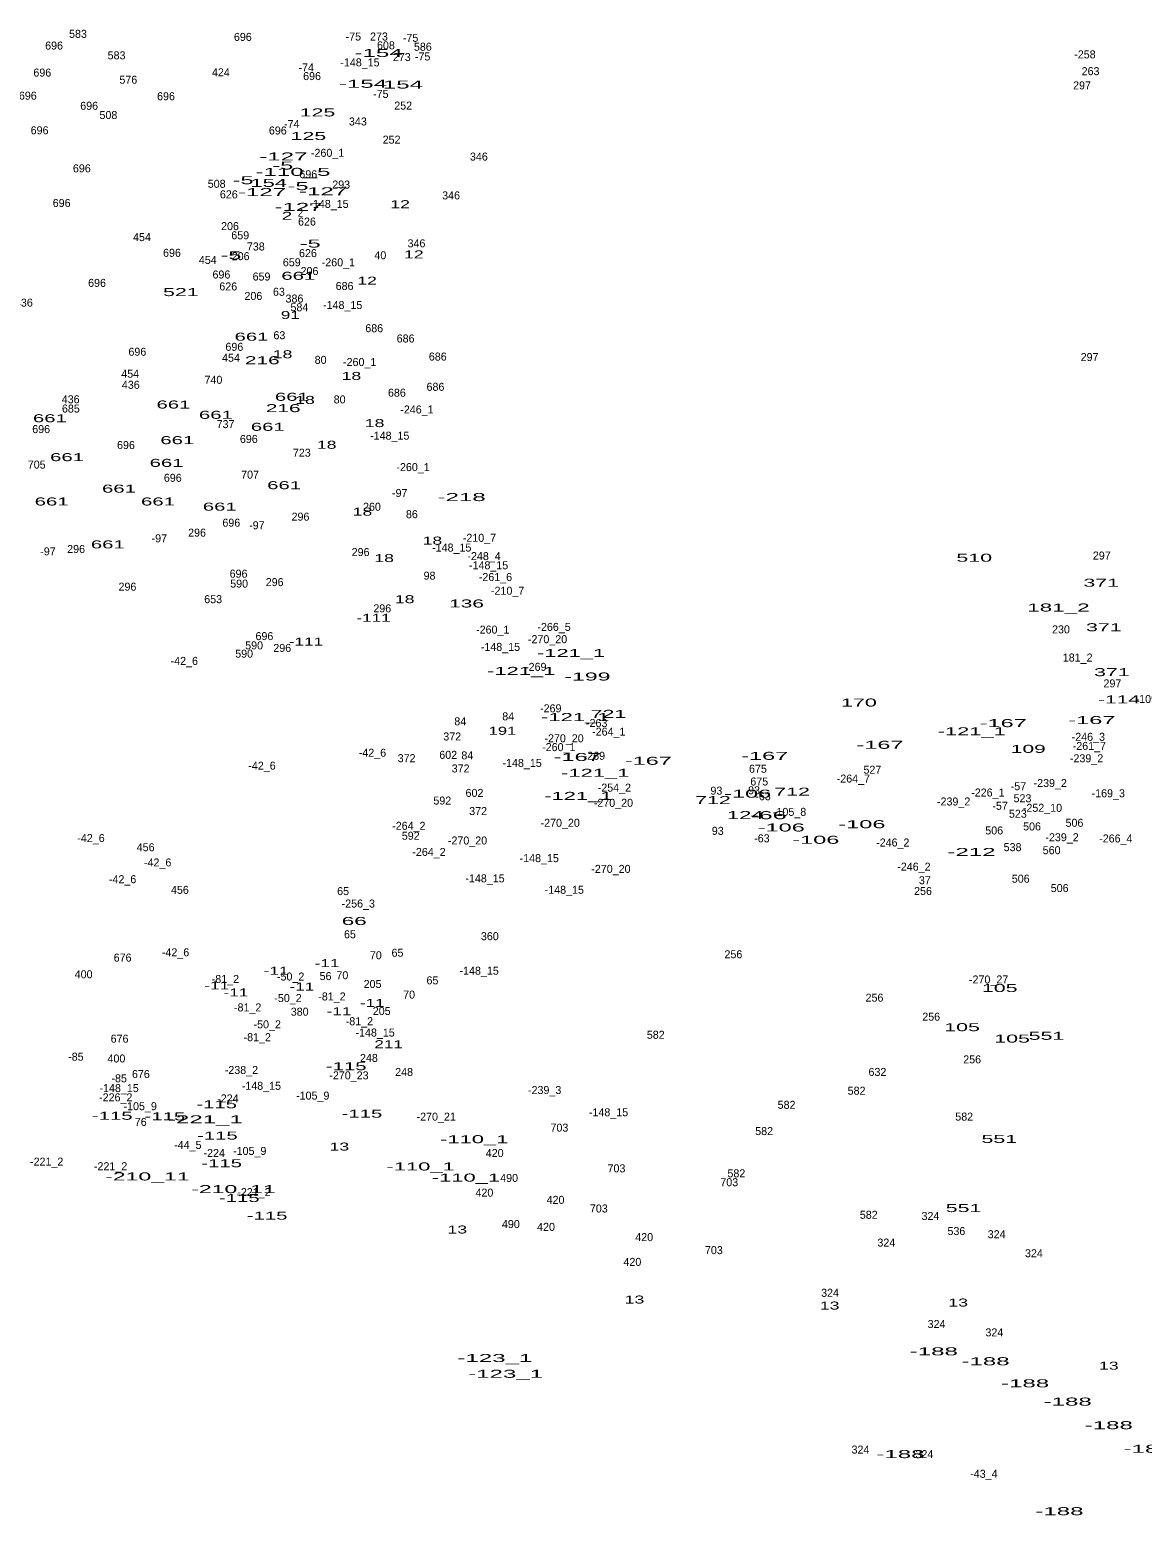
# Model space of a CAD drawing. Extents: x -658595 to -655205, y -1004347 to -1000147.
# Drawn here: x -656989 to -656433, y -1002977 to -1002234 of the extents above; entities that cross this region are included whole.
import ezdxf
from ezdxf.enums import TextEntityAlignment as Align

# ---------------------------------------------------------------- set-up
doc = ezdxf.new("R2010")
doc.units = 0
doc.header["$LTSCALE"] = 1.6
doc.layers.add('24', color=7, linetype='Continuous')

msp = doc.modelspace()

# ---------------------------------------------------------------- texts
at = {"layer": '24'}
for s, p in [('583', (-656964.917, -1002238.51)), ('696', (-656976.863, -1002244.38)), ('696', (-656882.493, -1002240.05)), ('-75', (-656827.231, -1002239.85)), ('273', (-656814.423, -1002239.85)), ('608', (-656810.937, -1002244.25)), ('-75', (-656798.621, -1002240.52)), ('586', (-656792.493, -1002244.96)), ('583', (-656945.617, -1002249.26)), ('-148_15', (-656823.923, -1002252.79)), ('273', (-656803.013, -1002250.13)), ('-75', (-656792.581, -1002249.83)), ('-258', (-656461.435, -1002248.78)), ('696', (-656982.753, -1002257.88)), ('576', (-656939.738, -1002261.45)), ('424', (-656893.466, -1002257.75)), ('-74', (-656850.825, -1002255.34)), ('696', (-656847.873, -1002259.64)), ('263', (-656458.613, -1002257.18)), ('-75', (-656813.501, -1002268.56)), ('297', (-656462.898, -1002264.28)), ('696', (-656990.003, -1002269.42)), ('696', (-656959.323, -1002274.48)), ('696', (-656920.903, -1002269.72)), ('252', (-656802.307, -1002274.38)), ('508', (-656949.711, -1002279.1)), ('-74', (-656858.025, -1002283.58)), ('343', (-656824.971, -1002282.33)), ('696', (-656984.113, -1002286.74)), ('696', (-656864.993, -1002286.85)), ('252', (-656808.107, -1002291.41)), ('-260_1', (-656840.106, -1002298.01)), ('696', (-656962.993, -1002305.77)), ('346', (-656764.467, -1002299.88)), ('508', (-656895.571, -1002313.48)), ('696', (-656849.763, -1002308.72)), ('293', (-656833.313, -1002313.86)), ('626', (-656889.498, -1002318.78)), ('346', (-656778.357, -1002319.29)), ('696', (-656973.073, -1002323.08)), ('-148_15', (-656839.403, -1002323.55)), ('206', (-656888.907, -1002334.65)), ('626', (-656850.418, -1002332.37)), ('454', (-656932.926, -1002340.15)), ('659', (-656883.788, -1002339.22)), ('346', (-656795.657, -1002343.26)), ('696', (-656917.923, -1002348)), ('206', (-656883.587, -1002349.68)), ('738', (-656876.013, -1002344.83)), ('626', (-656849.938, -1002348.16)), ('40', (-656813.735, -1002349.22)), ('454', (-656900.016, -1002351.56)), ('659', (-656858.018, -1002352.73)), ('206', (-656849.157, -1002357.1)), ('-260_1', (-656834.726, -1002352.76)), ('696', (-656955.383, -1002363.03)), ('696', (-656893.193, -1002358.85)), ('626', (-656889.778, -1002364.81)), ('659', (-656873.138, -1002359.86)), ('686', (-656831.618, -1002364.59)), ('436', (-656991.967, -1002372.91)), ('206', (-656877.217, -1002369.57)), ('63', (-656864.443, -1002367.48)), ('386', (-656856.673, -1002370.88)), ('584', (-656854.211, -1002375.21)), ('-148_15', (-656832.563, -1002374.11)), ('686', (-656816.788, -1002385.7)), ('696', (-656886.723, -1002395)), ('63', (-656864.213, -1002389.21)), ('686', (-656801.098, -1002390.84)), ('696', (-656935.223, -1002397.47)), ('454', (-656888.416, -1002400.46)), ('80', (-656843.591, -1002401.52)), ('-260_1', (-656824.066, -1002402.6)), ('686', (-656785.028, -1002399.88)), ('297', (-656459.098, -1002400.12)), ('454', (-656938.816, -1002408.45)), ('436', (-656938.517, -1002413.99)), ('740', (-656897.191, -1002411.49)), ('686', (-656786.168, -1002415)), ('436', (-656968.567, -1002421.23)), ('80', (-656834.081, -1002421.3)), ('686', (-656805.468, -1002417.95)), ('685', (-656968.483, -1002425.86)), ('-246_1', (-656795.436, -1002426.33)), ('696', (-656983.333, -1002436.14)), ('737', (-656891.129, -1002433.65)), ('-148_15', (-656809.033, -1002439.43)), ('696', (-656940.923, -1002444.12)), ('696', (-656879.503, -1002441.08)), ('705', (-656985.557, -1002453.89)), ('723', (-656852.993, -1002447.94)), ('696', (-656917.523, -1002460.49)), ('707', (-656878.882, -1002458.92)), ('-260_1', (-656797.376, -1002455.14)), ('-97', (-656804.045, -1002468.09)), ('260', (-656817.927, -1002474.96)), ('696', (-656888.243, -1002482.94)), ('-97', (-656875.475, -1002484.22)), ('296', (-656853.658, -1002479.92)), ('86', (-656797.973, -1002478.69)), ('-97', (-656924.245, -1002490.75)), ('296', (-656905.388, -1002487.91)), ('-210_7', (-656764.176, -1002490.5)), ('-97', (-656979.925, -1002497.28)), ('296', (-656965.858, -1002496.1)), ('296', (-656823.608, -1002497.62)), ('-148_15', (-656778.033, -1002495.36)), ('-248_4', (-656761.881, -1002499.64)), ('297', (-656453.008, -1002499.36)), ('-148_15', (-656759.593, -1002504.22)), ('696', (-656884.623, -1002508.44)), ('590', (-656884.347, -1002513.4)), ('296', (-656866.588, -1002512.65)), ('98', (-656789.133, -1002509.42)), ('-261_6', (-656756.187, -1002510.11)), ('296', (-656940.188, -1002514.93)), ('653', (-656897.333, -1002521.18)), ('-210_7', (-656750.096, -1002516.95)), ('296', (-656812.768, -1002525.77)), ('-260_1', (-656757.536, -1002536.39)), ('-266_5', (-656726.873, -1002535.04)), ('230', (-656473.411, -1002536.28)), ('696', (-656871.693, -1002539.64)), ('-270_20', (-656730.125, -1002541.18)), ('590', (-656881.847, -1002548.41)), ('590', (-656876.847, -1002544.28)), ('296', (-656862.788, -1002545.56)), ('-148_15', (-656753.683, -1002545.02)), ('181_2', (-656465.07, -1002550.36)), ('-42_6', (-656911.752, -1002552.04)), ('-269', (-656736.005, -1002555.01)), ('297', (-656447.688, -1002563.28)), ('-109_4', (-656427.78, -1002571.09)), ('84', (-656749.801, -1002579.77)), ('-269', (-656728.525, -1002575.76)), ('84', (-656773.771, -1002582.25)), ('-263', (-656705.55, -1002583.09)), ('-264_1', (-656699.536, -1002587.41)), ('372', (-656777.783, -1002589.83)), ('-260_1', (-656724.506, -1002595.15)), ('-270_20', (-656721.865, -1002590.73)), ('-246_3', (-656459.732, -1002590)), ('-261_7', (-656459.217, -1002594.55)), ('-42_6', (-656817.682, -1002597.94)), ('372', (-656800.603, -1002600.68)), ('602', (-656779.797, -1002599.01)), ('84', (-656770.251, -1002599.27)), ('-148_15', (-656742.843, -1002603.05)), ('-269', (-656706.725, -1002599.48)), ('-239_2', (-656460.618, -1002600.73)), ('-42_6', (-656872.902, -1002604.42)), ('372', (-656773.593, -1002605.81)), ('675', (-656624.948, -1002605.96)), ('-264_7', (-656577.218, -1002610.87)), ('527', (-656567.703, -1002606.44)), ('602', (-656766.667, -1002618.04)), ('-254_2', (-656696.707, -1002615.4)), ('93', (-656645.713, -1002616.93)), ('93', (-656626.873, -1002616.75)), ('675', (-656624.278, -1002612.34)), ('-226_1', (-656509.982, -1002617.84)), ('-57', (-656494.671, -1002614.69)), ('-239_2', (-656478.788, -1002613.1)), ('-169_3', (-656449.777, -1002618.23)), ('592', (-656782.753, -1002621.87)), ('-270_20', (-656697.195, -1002623)), ('-63', (-656622.39, -1002619.71)), ('-239_2', (-656527.088, -1002622.33)), ('-57', (-656503.851, -1002624.5)), ('523', (-656492.667, -1002620.72)), ('-252_10', (-656482.669, -1002625.5)), ('372', (-656764.843, -1002627.12)), ('-270_20', (-656723.795, -1002632.99)), ('-105_8', (-656609.11, -1002627.52)), ('523', (-656494.977, -1002628.45)), ('506', (-656466.667, -1002632.98)), ('-42_6', (-656958.402, -1002640.61)), ('-264_2', (-656799.492, -1002634.5)), ('592', (-656798.543, -1002639.46)), ('93', (-656645.033, -1002637.01)), ('-63', (-656622.96, -1002640.74)), ('506', (-656506.797, -1002636.82)), ('506', (-656487.887, -1002634.81)), ('-239_2', (-656472.878, -1002640.21)), ('456', (-656931.077, -1002645.21)), ('-264_2', (-656789.412, -1002647.56)), ('-270_20', (-656770.145, -1002641.83)), ('-246_2', (-656557.512, -1002642.84)), ('538', (-656497.607, -1002645.17)), ('560', (-656478.077, -1002646.69)), ('-266_4', (-656445.988, -1002640.82)), ('-42_6', (-656925.072, -1002652.81)), ('-148_15', (-656734.283, -1002650.66)), ('-246_2', (-656546.952, -1002654.92)), ('-42_6', (-656942.602, -1002661.19)), ('-148_15', (-656761.393, -1002660.77)), ('-270_20', (-656698.445, -1002656.03)), ('37', (-656541.473, -1002661.71)), ('506', (-656493.547, -1002660.93)), ('456', (-656913.957, -1002666.52)), ('65', (-656832.353, -1002667.13)), ('-148_15', (-656721.743, -1002666.47)), ('256', (-656542.403, -1002667.09)), ('506', (-656474.067, -1002665.63)), ('-256_3', (-656824.758, -1002673.36)), ('65', (-656828.933, -1002688.73)), ('360', (-656758.987, -1002689.69)), ('-42_6', (-656916.132, -1002697.75)), ('70', (-656815.997, -1002699.21)), ('65', (-656805.163, -1002697.95)), ('256', (-656637.203, -1002698.72)), ('676', (-656942.603, -1002700.39)), ('-148_15', (-656764.333, -1002706.93)), ('400', (-656962.089, -1002708.73)), ('-81_2', (-656891.216, -1002711.07)), ('-50_2', (-656858.586, -1002709.85)), ('56', (-656841.123, -1002709.64)), ('70', (-656832.727, -1002709.2)), ('205', (-656817.621, -1002713.57)), ('65', (-656787.683, -1002711.75)), ('-270_27', (-656509.587, -1002711.33)), ('-50_2', (-656859.916, -1002720.62)), ('-81_2', (-656837.926, -1002719.81)), ('70', (-656799.357, -1002718.9)), ('256', (-656566.653, -1002720.41)), ('-81_2', (-656880.076, -1002725.29)), ('380', (-656854.061, -1002727.43)), ('205', (-656813.051, -1002727.08)), ('-50_2', (-656870.296, -1002733.76)), ('-81_2', (-656824.206, -1002732.2)), ('256', (-656538.313, -1002729.92)), ('676', (-656944.123, -1002740.92)), ('-81_2', (-656875.276, -1002740.17)), ('-148_15', (-656816.353, -1002737.85)), ('582', (-656676.037, -1002738.98)), ('-85', (-656965.965, -1002749.93)), ('400', (-656945.689, -1002750.83)), ('248', (-656819.451, -1002750.54)), ('256', (-656517.823, -1002751.28)), ('676', (-656933.473, -1002758.61)), ('-238_2', (-656883.192, -1002756.57)), ('-270_23', (-656829.431, -1002759.27)), ('248', (-656801.851, -1002757.58)), ('632', (-656565.173, -1002757.55)), ('-148_15', (-656944.343, -1002765.63)), ('-85', (-656944.315, -1002760.74)), ('-148_15', (-656873.213, -1002764.49)), ('-239_3', (-656731.578, -1002766.61)), ('582', (-656575.617, -1002766.95)), ('-226_2', (-656946.038, -1002770.25)), ('-224', (-656889.959, -1002770.79)), ('-105_9', (-656847.536, -1002769.4)), ('582', (-656610.617, -1002773.99)), ('-105_9', (-656933.806, -1002774.68)), ('-270_21', (-656785.805, -1002779.93)), ('-148_15', (-656699.643, -1002777.73)), ('582', (-656521.797, -1002779.89)), ('76', (-656933.548, -1002782.55)), ('703', (-656724.197, -1002785.4)), ('582', (-656621.837, -1002787.12)), ('-44_5', (-656909.991, -1002794.05)), ('-221_2', (-656980.566, -1002802.41)), ('-224', (-656896.799, -1002798.09)), ('-105_9', (-656879.036, -1002797.06)), ('420', (-656756.555, -1002798.1)), ('-221_2', (-656948.616, -1002804.7)), ('490', (-656749.351, -1002810.57)), ('703', (-656695.667, -1002805.76)), ('582', (-656635.717, -1002808.24)), ('-221_2', (-656876.916, -1002817.63)), ('420', (-656761.695, -1002817.89)), ('703', (-656639.277, -1002812.7)), ('420', (-656726.135, -1002821.51)), ('703', (-656704.507, -1002825.83)), ('490', (-656748.481, -1002833.62)), ('582', (-656569.537, -1002828.98)), ('324', (-656538.671, -1002829.56)), ('420', (-656730.885, -1002835.01)), ('420', (-656681.815, -1002840.15)), ('536', (-656525.713, -1002837.12)), ('324', (-656505.581, -1002838.69)), ('703', (-656646.977, -1002846.66)), ('324', (-656560.731, -1002842.88)), ('324', (-656486.941, -1002848.2)), ('420', (-656687.715, -1002852.52)), ('324', (-656588.881, -1002867.99)), ('324', (-656535.631, -1002883.59)), ('324', (-656506.721, -1002887.78)), ('324', (-656573.661, -1002946.37)), ('324', (-656541.711, -1002948.66)), ('-43_4', (-656511.961, -1002958.48))]:
    msp.add_text(s, height=4, dxfattribs=at).set_placement(p, align=Align.CENTER)
for s, width, p in [('-154', 2.25, (-656814.606, -1002248.08)), ('-154', 2.25, (-656822.396, -1002263.49)), ('-154', 2.25, (-656804.426, -1002263.87)), ('125', 2, (-656845.157, -1002277.8)), ('125', 2, (-656849.717, -1002289.59)), ('-127', 2.25, (-656862.235, -1002299.84)), ('-5', 2.2, (-656862.474, -1002304.35)), ('-5', 2.2, (-656882.354, -1002311.7)), ('154', 2.05, (-656869.533, -1002313.04)), ('-110_5', 2.25, (-656857.414, -1002307.53)), ('-127', 2.25, (-656872.895, -1002317.62)), ('-5', 2.2, (-656854.874, -1002314.65)), ('-127', 2.25, (-656842.365, -1002317.24)), ('-127', 2.25, (-656854.635, -1002325.04)), ('2', 0.9, (-656853.679, -1002327.97)), ('12', 1.65, (-656803.827, -1002323.68)), ('2', 1.8, (-656860.421, -1002329.49)), ('-5', 2.2, (-656848.784, -1002343.38)), ('-5', 2.2, (-656888.434, -1002349.27)), ('12', 1.65, (-656796.977, -1002348.79)), ('661', 1.9, (-656854.757, -1002359.48)), ('12', 1.65, (-656820.367, -1002361.92)), ('521', 2, (-656913.467, -1002367.63)), ('91', 1.6, (-656858.743, -1002379.09)), ('661', 1.9, (-656878.137, -1002389.94)), ('216', 1.95, (-656872.763, -1002401.7)), ('18', 1.65, (-656862.617, -1002398.71)), ('18', 1.65, (-656828.197, -1002409.55)), ('661', 1.9, (-656917.177, -1002423.85)), ('661', 1.9, (-656857.967, -1002419.98)), ('18', 1.65, (-656851.397, -1002421.54)), ('661', 1.9, (-656978.947, -1002430.71)), ('661', 1.9, (-656895.947, -1002429)), ('216', 1.95, (-656862.303, -1002425.67)), ('661', 1.9, (-656869.997, -1002435)), ('18', 1.65, (-656816.597, -1002433.14)), ('661', 1.9, (-656915.247, -1002441.65)), ('18', 1.65, (-656840.557, -1002443.99)), ('661', 1.9, (-656970.377, -1002450.16)), ('661', 1.9, (-656920.607, -1002453.03)), ('661', 1.9, (-656944.417, -1002465.9)), ('661', 1.9, (-656861.837, -1002464.19)), ('661', 1.9, (-656978.087, -1002472.34)), ('661', 1.9, (-656924.897, -1002472.34)), ('661', 1.9, (-656894.017, -1002474.91)), ('-218', 2.25, (-656773.091, -1002470.13)), ('18', 1.65, (-656822.677, -1002477.42)), ('18', 1.65, (-656787.687, -1002491.88)), ('661', 1.9, (-656949.997, -1002493.79)), ('18', 1.65, (-656811.837, -1002500.63)), ('510', 2, (-656516.784, -1002500.45)), ('371', 2, (-656453.293, -1002512.95)), ('18', 1.65, (-656801.567, -1002521.18)), ('136', 1.95, (-656770.623, -1002523.33)), ('181_2', 2.1, (-656474.685, -1002525.34)), ('-111', 1.6, (-656817.133, -1002530.5)), ('371', 2, (-656451.963, -1002535.21)), ('-111', 1.6, (-656850.933, -1002542.41)), ('-121_1', 2.05, (-656718.374, -1002548.09)), ('-121_1', 2.05, (-656743.274, -1002557.04)), ('371', 2, (-656447.963, -1002557.66)), ('-199', 2.15, (-656710.199, -1002559.85)), ('170', 2, (-656574.429, -1002572.86)), ('-114', 1.95, (-656444.402, -1002571.29)), ('-121_1', 2.05, (-656716.264, -1002580.11)), ('721', 2, (-656699.683, -1002578.52)), ('191', 1.55, (-656752.689, -1002586.98)), ('-121_1', 2.05, (-656518.044, -1002587.23)), ('-167', 2.2, (-656502.269, -1002583.14)), ('-167', 2.2, (-656457.959, -1002581.62)), ('-167', 2.2, (-656563.909, -1002593.99)), ('109', 1.95, (-656489.749, -1002596.02)), ('-167', 2.2, (-656715.289, -1002600.08)), ('-167', 2.2, (-656679.729, -1002601.98)), ('-167', 2.2, (-656621.529, -1002599.51)), ('-121_1', 2.05, (-656706.264, -1002608)), ('-106', 2.2, (-656630.071, -1002618.42)), ('712', 2, (-656607.853, -1002617.42)), ('-121_1', 2.05, (-656714.724, -1002619.54)), ('712', 2, (-656647.433, -1002621.61)), ('124', 2.05, (-656631.283, -1002629.12)), ('-66', 2.35, (-656619.663, -1002629.18)), ('-106', 2.2, (-656613.271, -1002635.32)), ('-106', 2.2, (-656572.951, -1002633.69)), ('-106', 2.2, (-656595.991, -1002641.47)), ('-212', 2.25, (-656518.161, -1002647.58)), ('66', 2.1, (-656826.791, -1002682.07)), ('-11', 1.6, (-656865.877, -1002706.96)), ('-11', 1.6, (-656840.397, -1002703.16)), ('-11', 1.6, (-656895.547, -1002714.29)), ('-11', 1.6, (-656852.947, -1002714.86)), ('-11', 1.6, (-656885.947, -1002717.81)), ('105', 2, (-656504.034, -1002715.59)), ('-11', 1.6, (-656834.397, -1002727.22)), ('-11', 1.6, (-656817.757, -1002723.04)), ('105', 2, (-656522.864, -1002735.17)), ('211', 1.6, (-656809.584, -1002743.69)), ('105', 2, (-656497.854, -1002740.88)), ('551', 2, (-656480.657, -1002739.49)), ('-115', 1.9, (-656830.787, -1002754.69)), ('-115', 1.9, (-656895.577, -1002773.72)), ('-115', 1.9, (-656947.777, -1002779.47)), ('-115', 1.9, (-656921.467, -1002779.75)), ('-221_1', 2.25, (-656901.197, -1002781.24)), ('-115', 1.9, (-656822.917, -1002778.41)), ('-115', 1.9, (-656895.197, -1002789.37)), ('13', 1.65, (-656834.227, -1002794.87)), ('-110_1', 2.05, (-656766.79, -1002791.17)), ('551', 2, (-656504.237, -1002791.05)), ('-115', 1.9, (-656893.087, -1002803.2)), ('-210_11', 2.15, (-656930.22, -1002809.8)), ('-110_1', 2.05, (-656793.58, -1002804.81)), ('-110_1', 2.05, (-656770.92, -1002810.38)), ('-210_11', 2.15, (-656887.19, -1002816.13)), ('-115', 1.9, (-656884.257, -1002820.59)), ('551', 2, (-656522.117, -1002825.62)), ('-115', 1.9, (-656870.337, -1002829.42)), ('13', 1.65, (-656775.267, -1002836.34)), ('13', 1.65, (-656686.647, -1002871.35)), ('13', 1.65, (-656589.077, -1002874.36)), ('13', 1.65, (-656524.797, -1002872.85)), ('-123_1', 2.25, (-656756.467, -1002900.6)), ('-188', 2.25, (-656536.991, -1002897.26)), ('-188', 2.25, (-656511.131, -1002902.21)), ('13', 1.65, (-656449.487, -1002904.42)), ('-123_1', 2.25, (-656751.087, -1002908.48)), ('-188', 2.25, (-656491.351, -1002913.24)), ('-188', 2.25, (-656470.051, -1002922.38)), ('-188', 2.25, (-656449.511, -1002934.17)), ('-188', 2.25, (-656553.691, -1002948.63)), ('-188', 2.25, (-656430.111, -1002945.97)), ('-188', 2.25, (-656474.191, -1002977.17))]:
    msp.add_text(s, height=4, dxfattribs=dict(at, width=width)).set_placement(p, align=Align.CENTER)

doc.saveas('drawing.dxf')
